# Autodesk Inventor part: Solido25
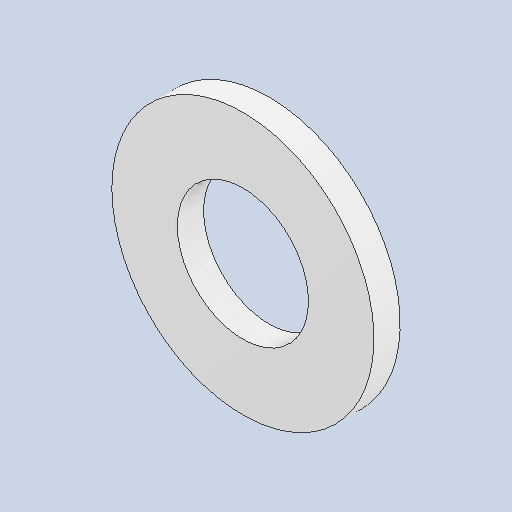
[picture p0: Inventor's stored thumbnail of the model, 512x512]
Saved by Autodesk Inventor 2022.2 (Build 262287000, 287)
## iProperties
Created: 2024-10
Part Number: Solido25
Material: Generico
Document SubType Name: Modeling
Designer: 18907419
Density: 1 g/cm^3
Appearance: Default
Author: 18907419
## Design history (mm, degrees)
feature "Solido25"
node "Solido1"
